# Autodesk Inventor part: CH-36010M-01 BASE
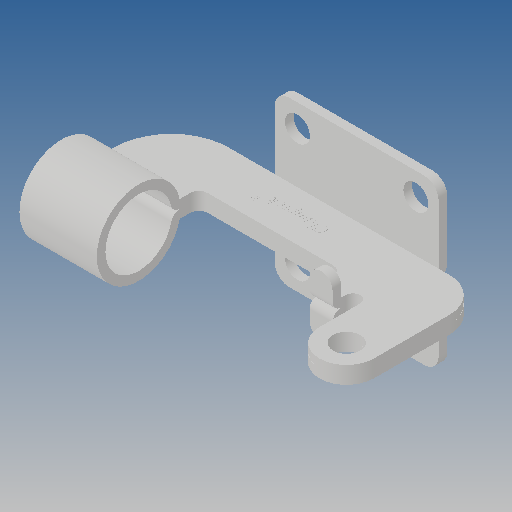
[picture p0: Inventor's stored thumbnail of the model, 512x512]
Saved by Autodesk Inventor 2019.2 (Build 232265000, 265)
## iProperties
Created: 2012-09
Part Number: CH-36010M-01 BASE
Material: Ogólny
Document SubType Name: Modeling
Designer: CADENGINEERING4
Density: 1 g/cm^3
Appearance: Domyślna
Author: CADENGINEERING4
Revision Number: ÈÎºÎ
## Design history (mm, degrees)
feature "ÇÐ³ý-À­Éì2"
feature "ÇÐ³ý-À­Éì5"
node "Bryła1"
node "Bryła2"
